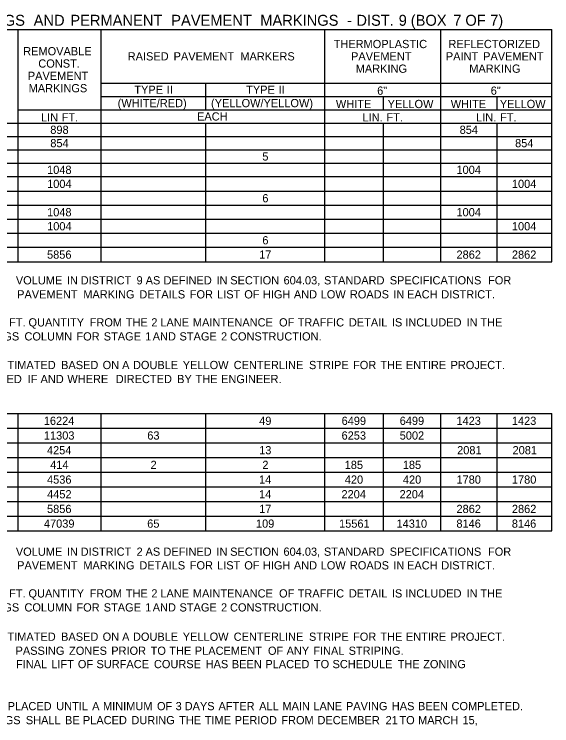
# Model space of a CAD drawing. Extents: x 544255 to 1930787, y -1947044 to 596640.
# Drawn here: x 546773 to 547165, y -1946826 to -1946306 of the extents above; entities that cross this region are included whole.
import ezdxf

# ---------------------------------------------------------------- set-up
doc = ezdxf.new("R2010")
doc.units = 0
doc.layers.add('Default', color=7, linetype='Continuous')

msp = doc.modelspace()

# ---------------------------------------------------------------- linework, layer by layer
at = {"layer": 'Default'}
for p, q in [((546530.88, -1946317.48), (547165.12, -1946317.48)), ((546530.88, -1946317.48), (546836.06, -1946317.48)), ((546775.61, -1946487.13), (546775.61, -1946317.48)), ((546836.06, -1946487.13), (546836.06, -1946317.48)), ((546999.37, -1946487.13), (546999.37, -1946317.48)), ((547084.2, -1946385.73), (547084.2, -1946317.48)), ((547084.2, -1946487.13), (547084.2, -1946317.48)), ((547165.12, -1946487.13), (547165.12, -1946317.48)), ((546836.06, -1946356.48), (547165.12, -1946356.48)), ((546912.6, -1946375.98), (546912.6, -1946356.48)), ((546836.06, -1946366.23), (547165.12, -1946366.23)), ((547042.27, -1946375.98), (547042.27, -1946366.23)), ((547125.15, -1946375.98), (547125.15, -1946366.23)), ((546775.61, -1946375.98), (547165.12, -1946375.98)), ((546775.61, -1946385.73), (546775.61, -1946375.98)), ((546676.16, -1946385.73), (547165.12, -1946385.73)), ((546912.6, -1946487.13), (546912.6, -1946385.73)), ((546999.37, -1946385.73), (547084.2, -1946385.73)), ((547042.27, -1946487.13), (547042.27, -1946385.73)), ((547084.2, -1946385.73), (547165.12, -1946385.73)), ((547125.15, -1946487.13), (547125.15, -1946385.73)), ((546715.65, -1946395.48), (547165.12, -1946395.48)), ((546715.65, -1946405.23), (547165.12, -1946405.23)), ((546530.88, -1946414.98), (547165.12, -1946414.98)), ((546715.65, -1946424.73), (547165.12, -1946424.73)), ((546715.65, -1946435.46), (547165.12, -1946435.46)), ((546530.88, -1946445.7), (547165.12, -1946445.7)), ((546715.65, -1946455.93), (547165.12, -1946455.93)), ((546715.65, -1946466.17), (547165.12, -1946466.17)), ((546530.88, -1946476.41), (547165.12, -1946476.41)), ((546775.61, -1946487.13), (546775.61, -1946476.41)), ((546530.88, -1946487.13), (547165.12, -1946487.13)), ((546530.88, -1946597.8), (547165.12, -1946597.8)), ((546530.88, -1946597.8), (547165.12, -1946597.8)), ((546775.61, -1946683.6), (546775.61, -1946597.8)), ((546775.61, -1946683.6), (546775.61, -1946597.8)), ((546836.06, -1946683.6), (546836.06, -1946597.8)), ((546912.6, -1946683.6), (546912.6, -1946597.8)), ((546999.37, -1946683.6), (546999.37, -1946597.8)), ((547042.27, -1946683.6), (547042.27, -1946597.8)), ((547084.2, -1946683.6), (547084.2, -1946597.8)), ((547125.15, -1946683.6), (547125.15, -1946597.8)), ((547165.12, -1946683.6), (547165.12, -1946597.8)), ((546530.88, -1946608.52), (547165.12, -1946608.52)), ((546530.88, -1946619.25), (547165.12, -1946619.25)), ((546530.88, -1946629.97), (547165.12, -1946629.97)), ((546530.88, -1946640.7), (547165.12, -1946640.7)), ((546530.88, -1946651.42), (547165.12, -1946651.42)), ((546530.88, -1946662.15), (547165.12, -1946662.15)), ((546530.88, -1946672.87), (547165.12, -1946672.87)), ((546530.88, -1946683.6), (547165.12, -1946683.6))]:
    msp.add_line(p, q, dxfattribs=at)

# ---------------------------------------------------------------- texts
for s, height, p in [(' MARKINGS', 8, (546720.51, -1946314.66)), (' AND', 8, (546783.92, -1946314.66)), (' PERMANENT', 8, (546810.69, -1946314.66)), (' PAVEMENT', 8, (546884.37, -1946314.66)), (' MARKINGS', 8, (546949.35, -1946314.66)), (' DIST.', 8, (547019.51, -1946314.66)), (' 9', 8, (547050.41, -1946314.66)), (' (BOX', 8, (547059.21, -1946314.66)), (' 7', 8, (547090.25, -1946314.66)), (' OF', 8, (547099.07, -1946314.66)), (' 7)', 8, (547117.18, -1946314.66)), (' -', 8, (547012.77, -1946314.66)), ('THERMOPLASTIC', 6, (547005.9, -1946330.98)), ('REFLECTORIZED', 6, (547089.7, -1946330.98)), ('REMOVABLE', 6, (546779.26, -1946336.23)), ('RAISED', 6, (546855.56, -1946339.98)), (' PAVEMENT', 6, (546886.82, -1946339.98)), (' MARKERS', 6, (546935.56, -1946339.98)), ('PAVEMENT', 6, (547018.58, -1946339.98)), ('PAINT', 6, (547087.8, -1946339.98)), (' PAVEMENT', 6, (547112.78, -1946339.98)), ('CONST.', 6, (546790.29, -1946345.23)), ('MARKING', 6, (547022.01, -1946348.98)), ('MARKING', 6, (547104.89, -1946348.98)), ('PAVEMENT', 6, (546782.63, -1946354.23)), ('MARKINGS', 6, (546783.22, -1946363.23)), ('TYPE', 6, (546860.37, -1946364.36)), (' II', 6, (546881.85, -1946364.36)), ('TYPE', 6, (546942.02, -1946364.36)), (' II', 6, (546963.51, -1946364.36)), ('6"', 6, (547037.68, -1946365.03)), ('6"', 6, (547120.55, -1946365.03)), ('(WHITE/RED)', 6, (546848.24, -1946374.11)), ('(YELLOW/YELLOW)', 6, (546916.38, -1946374.11)), ('WHITE', 6, (547007.53, -1946374.78)), ('YELLOW', 6, (547045.31, -1946374.78)), ('WHITE', 6, (547091.38, -1946374.78)), ('YELLOW', 6, (547127.21, -1946374.78)), ('LIN', 6, (546792.26, -1946384.53)), (' FT.', 6, (546805.09, -1946384.53)), ('EACH', 6, (546906.16, -1946383.86)), ('LIN.', 6, (547026.99, -1946384.53)), (' FT.', 6, (547042.25, -1946384.53)), ('LIN.', 6, (547109.87, -1946384.53)), (' FT.', 6, (547125.13, -1946384.53)), ('898', 6, (546799.03, -1946393.61)), ('854', 6, (547097.88, -1946393.61)), ('854', 6, (546799.05, -1946403.36)), ('854', 6, (547138.35, -1946403.36)), ('5', 6, (546953.82, -1946413.11)), ('1048', 6, (546796.7, -1946422.86)), ('1004', 6, (547095.55, -1946422.86)), ('1004', 6, (546796.72, -1946433.1)), ('1004', 6, (547136.02, -1946433.1)), ('6', 6, (546953.84, -1946443.58)), ('1048', 6, (546796.7, -1946453.81)), ('1004', 6, (547095.55, -1946453.81)), ('1004', 6, (546796.72, -1946464.05)), ('1004', 6, (547136.02, -1946464.05)), ('6', 6, (546953.84, -1946474.29)), ('5856', 6, (546796.66, -1946484.77)), ('17', 6, (546951.51, -1946484.77)), ('2862', 6, (547095.56, -1946484.77)), ('2862', 6, (547136.02, -1946484.77)), (' VOLUME', 6, (546771.67, -1946503.54)), (' IN', 6, (546808.95, -1946503.54)), (' DISTRICT', 6, (546818.98, -1946503.54)), (' 9', 6, (546859.79, -1946503.54)), (' AS', 6, (546866.41, -1946503.54)), (' DEFINED', 6, (546879.48, -1946503.54)), (' IN', 6, (546918.16, -1946503.54)), (' SECTION', 6, (546928.19, -1946503.54)), (' 604.03,', 6, (546967.1, -1946503.54)), (' STANDARD', 6, (546996.63, -1946503.54)), (' SPECIFICATIONS', 6, (547044.63, -1946503.54)), (' FOR', 6, (547116.4, -1946503.54)), (' PAVEMENT', 6, (546772.6, -1946513.78)), (' MARKING', 6, (546820.88, -1946513.78)), (' DETAILS', 6, (546861.81, -1946513.78)), (' FOR', 6, (546898.65, -1946513.78)), (' LIST', 6, (546918.56, -1946513.78)), (' OF', 6, (546938.42, -1946513.78)), (' HIGH', 6, (546952.01, -1946513.78)), (' AND', 6, (546974.62, -1946513.78)), (' LOW', 6, (546994.2, -1946513.78)), (' ROADS', 6, (547015.52, -1946513.78)), (' IN', 6, (547047.23, -1946513.78)), (' EACH', 6, (547057.25, -1946513.78)), (' DISTRICT.', 6, (547082.2, -1946513.78)), (' FT.', 6, (546766.74, -1946534.25)), (' QUANTITY', 6, (546780.9, -1946534.25)), (' FROM', 6, (546825.56, -1946534.25)), (' THE', 6, (546851.94, -1946534.25)), (' 2', 6, (546870.58, -1946534.25)), (' LANE', 6, (546877.13, -1946534.25)), (' MAINTENANCE', 6, (546900.91, -1946534.25)), (' OF', 6, (546963.81, -1946534.25)), (' TRAFFIC', 6, (546977.4, -1946534.25)), (' DETAIL', 6, (547014.79, -1946534.25)), (' IS', 6, (547046.17, -1946534.25)), (' INCLUDED', 6, (547055.98, -1946534.25)), (' IN', 6, (547100.72, -1946534.25)), (' THE', 6, (547110.74, -1946534.25)), (' MARKINGS', 6, (546731.32, -1946544.49)), (' COLUMN', 6, (546777.93, -1946544.49)), (' FOR', 6, (546815.9, -1946544.49)), (' STAGE', 6, (546835.81, -1946544.49)), (' 1', 6, (546866.11, -1946544.49)), (' AND', 6, (546871.56, -1946544.49)), (' STAGE', 6, (546891.14, -1946544.49)), (' 2', 6, (546921.44, -1946544.49)), (' CONSTRUCTION.', 6, (546927.99, -1946544.49)), (' ESTIMATED', 6, (546754.84, -1946565.4)), (' BASED', 6, (546804.7, -1946565.4)), (' ON', 6, (546835.01, -1946565.4)), (' A', 6, (546849.22, -1946565.4)), (' DOUBLE', 6, (546857.16, -1946565.4)), (' YELLOW', 6, (546893.51, -1946565.4)), (' CENTERLINE', 6, (546930.69, -1946565.4)), (' STRIPE', 6, (546985.67, -1946565.4)), (' FOR', 6, (547017.84, -1946565.4)), (' THE', 6, (547037.75, -1946565.4)), (' ENTIRE', 6, (547056.4, -1946565.4)), (' PROJECT.', 6, (547089.02, -1946565.4)), (' DETERMINED', 6, (546722.97, -1946575.63)), (' IF', 6, (546780.28, -1946575.63)), (' AND', 6, (546789.67, -1946575.63)), (' WHERE', 6, (546809.26, -1946575.63)), ('  DIRECTED', 6, (546842.34, -1946575.63)), (' BY', 6, (546889.41, -1946575.63)), (' THE', 6, (546902.85, -1946575.63)), (' ENGINEER.', 6, (546921.5, -1946575.63)), ('16224', 6, (546794.28, -1946606.16)), ('49', 6, (546951.52, -1946606.16)), ('6499', 6, (547011.7, -1946606.16)), ('6499', 6, (547054.11, -1946606.16)), ('1423', 6, (547095.53, -1946606.16)), ('1423', 6, (547135.99, -1946606.16)), ('11303', 6, (546794.36, -1946616.88)), ('63', 6, (546869.85, -1946616.88)), ('6253', 6, (547011.68, -1946616.88)), ('5002', 6, (547054.12, -1946616.88)), ('4254', 6, (546796.61, -1946627.61)), ('13', 6, (546951.5, -1946627.61)), ('2081', 6, (547096.03, -1946627.61)), ('2081', 6, (547136.49, -1946627.61)), ('414', 6, (546798.94, -1946638.33)), ('2', 6, (546872.21, -1946638.33)), ('2', 6, (546953.86, -1946638.33)), ('185', 6, (547013.96, -1946638.33)), ('185', 6, (547056.37, -1946638.33)), ('4536', 6, (546796.66, -1946649.06)), ('14', 6, (546951.42, -1946649.06)), ('420', 6, (547014.04, -1946649.06)), ('420', 6, (547056.45, -1946649.06)), ('1780', 6, (547095.56, -1946649.06)), ('1780', 6, (547136.02, -1946649.06)), ('4452', 6, (546796.72, -1946659.78)), ('14', 6, (546951.42, -1946659.78)), ('2204', 6, (547011.6, -1946659.78)), ('2204', 6, (547054.01, -1946659.78)), ('5856', 6, (546796.66, -1946670.51)), ('17', 6, (546951.51, -1946670.51)), ('2862', 6, (547095.56, -1946670.51)), ('2862', 6, (547136.02, -1946670.51)), ('47039', 6, (546794.38, -1946681.23)), ('65', 6, (546869.79, -1946681.23)), ('109', 6, (546949.19, -1946681.23)), ('15561', 6, (547009.85, -1946681.23)), ('14310', 6, (547051.79, -1946681.23)), ('8146', 6, (547095.5, -1946681.23)), ('8146', 6, (547135.96, -1946681.23)), (' VOLUME', 6, (546771.67, -1946701.71)), (' IN', 6, (546808.95, -1946701.71)), (' DISTRICT', 6, (546818.98, -1946701.71)), (' 2', 6, (546859.79, -1946701.71)), (' AS', 6, (546866.34, -1946701.71)), (' DEFINED', 6, (546879.41, -1946701.71)), (' IN', 6, (546918.09, -1946701.71)), (' SECTION', 6, (546928.12, -1946701.71)), (' 604.03,', 6, (546967.02, -1946701.71)), (' STANDARD', 6, (546996.56, -1946701.71)), (' SPECIFICATIONS', 6, (547044.56, -1946701.71)), (' FOR', 6, (547116.33, -1946701.71)), (' PAVEMENT', 6, (546772.6, -1946711.7)), (' MARKING', 6, (546820.88, -1946711.7)), (' DETAILS', 6, (546861.81, -1946711.7)), (' FOR', 6, (546898.65, -1946711.7)), (' LIST', 6, (546918.56, -1946711.7)), (' OF', 6, (546938.42, -1946711.7)), (' HIGH', 6, (546952.01, -1946711.7)), (' AND', 6, (546974.62, -1946711.7)), (' LOW', 6, (546994.2, -1946711.7)), (' ROADS', 6, (547015.52, -1946711.7)), (' IN', 6, (547047.23, -1946711.7)), (' EACH', 6, (547057.25, -1946711.7)), (' DISTRICT.', 6, (547082.2, -1946711.7)), (' FT.', 6, (546766.74, -1946732.18)), (' QUANTITY', 6, (546780.9, -1946732.18)), (' FROM', 6, (546825.56, -1946732.18)), (' THE', 6, (546851.94, -1946732.18)), (' 2', 6, (546870.58, -1946732.18)), (' LANE', 6, (546877.13, -1946732.18)), (' MAINTENANCE', 6, (546900.91, -1946732.18)), (' OF', 6, (546963.81, -1946732.18)), (' TRAFFIC', 6, (546977.4, -1946732.18)), (' DETAIL', 6, (547014.79, -1946732.18)), (' IS', 6, (547046.17, -1946732.18)), (' INCLUDED', 6, (547055.98, -1946732.18)), (' IN', 6, (547100.72, -1946732.18)), (' THE', 6, (547110.74, -1946732.18)), (' MARKINGS', 6, (546731.32, -1946742.41)), (' COLUMN', 6, (546777.93, -1946742.41)), (' FOR', 6, (546815.9, -1946742.41)), (' STAGE', 6, (546835.81, -1946742.41)), (' 1', 6, (546866.11, -1946742.41)), (' AND', 6, (546871.56, -1946742.41)), (' STAGE', 6, (546891.14, -1946742.41)), (' 2', 6, (546921.44, -1946742.41)), (' CONSTRUCTION.', 6, (546927.99, -1946742.41)), (' ESTIMATED', 6, (546754.84, -1946763.81)), (' BASED', 6, (546804.7, -1946763.81)), (' ON', 6, (546835.01, -1946763.81)), (' A', 6, (546849.22, -1946763.81)), (' DOUBLE', 6, (546857.16, -1946763.81)), (' YELLOW', 6, (546893.51, -1946763.81)), (' CENTERLINE', 6, (546930.69, -1946763.81)), (' STRIPE', 6, (546985.67, -1946763.81)), (' FOR', 6, (547017.84, -1946763.81)), (' THE', 6, (547037.75, -1946763.81)), (' ENTIRE', 6, (547056.4, -1946763.81)), (' PROJECT.', 6, (547089.02, -1946763.81)), (' PASSING', 6, (546771.44, -1946774.05)), (' ZONES', 6, (546810.52, -1946774.05)), (' PRIOR', 6, (546841.3, -1946774.05)), (' TO', 6, (546870.06, -1946774.05)), (' THE', 6, (546883.66, -1946774.05)), (' PLACEMENT', 6, (546902.31, -1946774.05)), (' OF', 6, (546955.71, -1946774.05)), (' ANY', 6, (546969.3, -1946774.05)), (' FINAL', 6, (546988.8, -1946774.05)), (' STRIPING.', 6, (547014.59, -1946774.05)), (' FINAL', 6, (546771.76, -1946783.8)), (' LIFT', 6, (546797.54, -1946783.8)), (' OF', 6, (546816.93, -1946783.8)), (' SURFACE', 6, (546830.52, -1946783.8)), (' COURSE', 6, (546872.47, -1946783.8)), (' HAS', 6, (546910.22, -1946783.8)), (' BEEN', 6, (546929.35, -1946783.8)), (' PLACED', 6, (546953.82, -1946783.8)), (' TO', 6, (546989.25, -1946783.8)), (' SCHEDULE', 6, (547002.85, -1946783.8)), (' THE', 6, (547050.39, -1946783.8)), (' ZONING', 6, (547069.03, -1946783.8)), (' PLACED', 6, (546765.67, -1946814.51)), (' UNTIL', 6, (546801.1, -1946814.51)), (' A', 6, (546827.35, -1946814.51)), (' MINIMUM', 6, (546835.28, -1946814.51)), (' OF', 6, (546874.7, -1946814.51)), (' 3', 6, (546888.28, -1946814.51)), (' DAYS', 6, (546894.89, -1946814.51)), (' AFTER', 6, (546919.61, -1946814.51)), (' ALL', 6, (546949.31, -1946814.51)), (' MAIN', 6, (546966.26, -1946814.51)), (' LANE', 6, (546988.86, -1946814.51)), (' PAVING', 6, (547012.64, -1946814.51)), (' HAS', 6, (547046.12, -1946814.51)), (' BEEN', 6, (547065.25, -1946814.51)), (' COMPLETED.', 6, (547089.73, -1946814.51)), (' MARKINGS', 6, (546732.33, -1946824.75)), (' SHALL', 6, (546778.94, -1946824.75)), (' BE', 6, (546807.54, -1946824.75)), (' PLACED', 6, (546820.6, -1946824.75)), (' DURING', 6, (546856.03, -1946824.75)), (' THE', 6, (546890.9, -1946824.75)), (' TIME', 6, (546909.55, -1946824.75)), (' PERIOD', 6, (546931.46, -1946824.75)), (' FROM', 6, (546965.48, -1946824.75)), (' DECEMBER', 6, (546991.86, -1946824.75)), (' 21', 6, (547041.59, -1946824.75)), (' TO', 6, (547051.7, -1946824.75)), (' MARCH', 6, (547065.29, -1946824.75)), (' 15,', 6, (547097.69, -1946824.75))]:
    msp.add_text(s, height=height, dxfattribs=at).set_placement(p)

doc.saveas('drawing.dxf')
